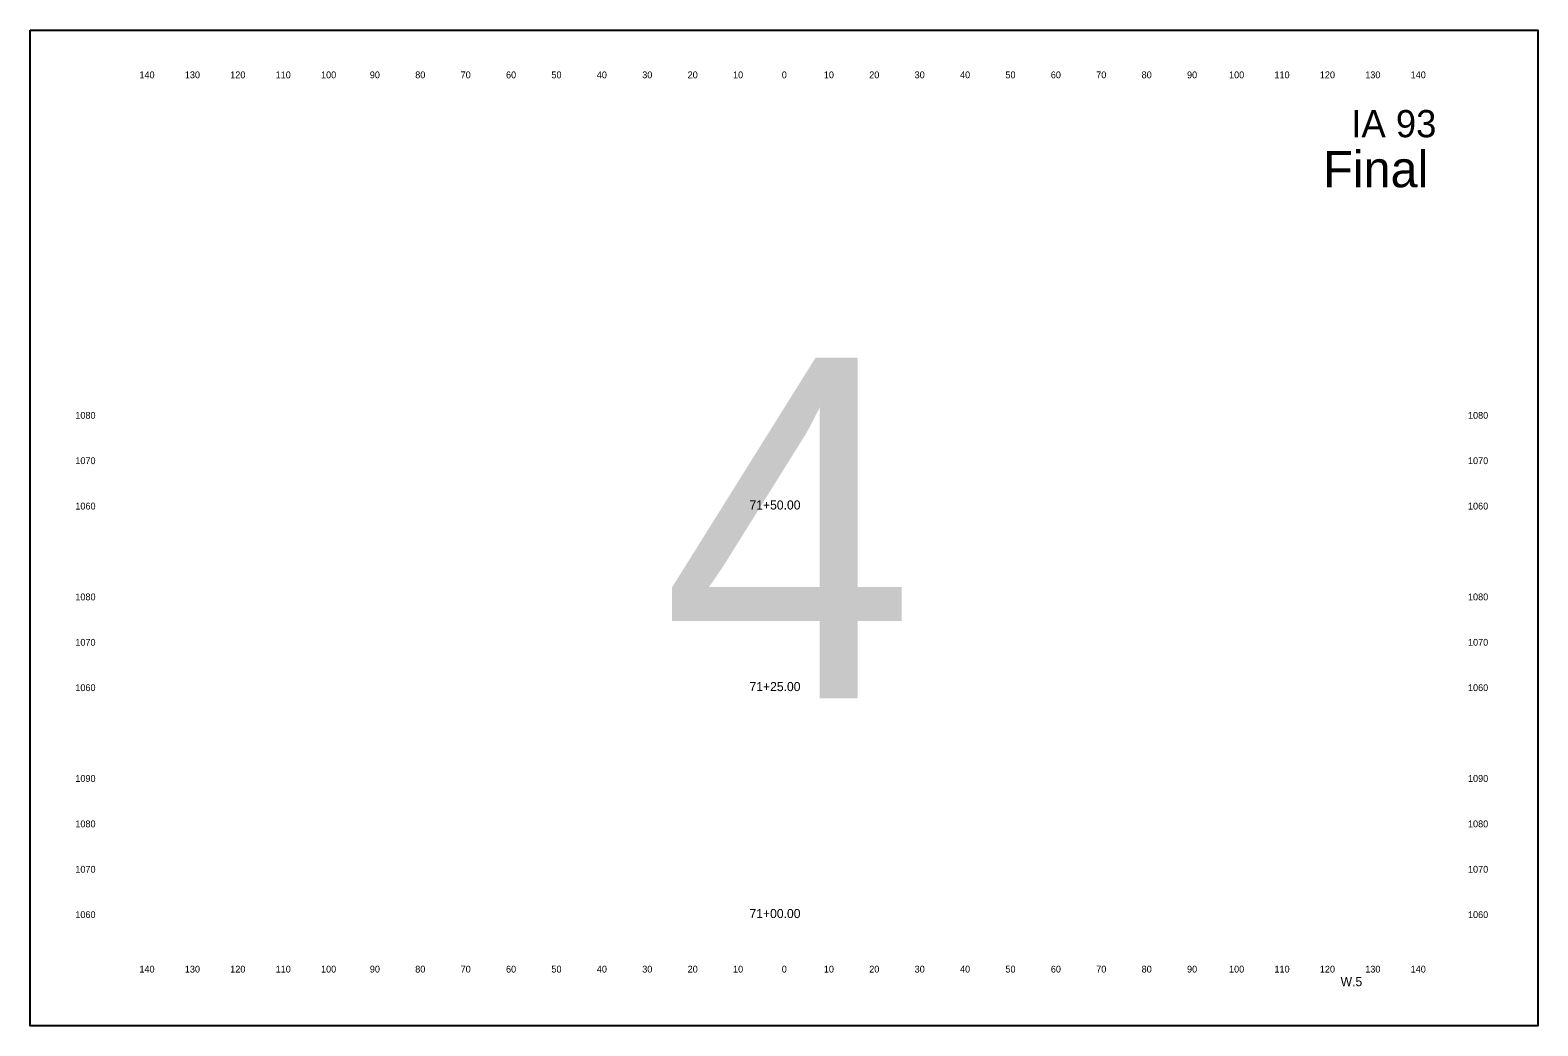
# Model space of a CAD drawing. Extents: x 10123 to 11535, y 9730 to 9950.
# Drawn here: x 11203.2 to 11535.3, y 9730.3 to 9949.6 of the extents above; entities that cross this region are included whole.
import ezdxf

# ---------------------------------------------------------------- set-up
doc = ezdxf.new("R2010")
doc.units = 0
for name, color, linetype in [('dsn3DSubgradeHingePoint', 7, 'Continuous'), ('dsnXSEarthwork', 7, 'Continuous'), ('dsnXsPCCPavement', 7, 'Continuous'), ('dsnXsShldrEarthFill', 7, 'Continuous')]:
    doc.layers.add(name, color=color, linetype=linetype)

msp = doc.modelspace()

# ---------------------------------------------------------------- linework, layer by layer
at = {"layer": 'dsnXsShldrEarthFill'}
msp.add_lwpolyline([(11203.21, 9949.6), (11535.29, 9949.6), (11535.29, 9730.26), (11203.21, 9730.26)], close=True, dxfattribs=at)

# ---------------------------------------------------------------- texts
at = {"layer": 'dsn3DSubgradeHingePoint'}
for s, height, p in [('140', 1.5, (11227.27, 9939)), ('130', 1.5, (11237.27, 9939)), ('120', 1.5, (11247.27, 9939)), ('110', 1.5, (11257.27, 9939)), ('100', 1.5, (11267.27, 9939)), ('90', 1.5, (11278.02, 9939)), ('80', 1.5, (11288.02, 9939)), ('70', 1.5, (11298.02, 9939)), ('60', 1.5, (11308.02, 9939)), ('50', 1.5, (11318.02, 9939)), ('40', 1.5, (11328.02, 9939)), ('30', 1.5, (11338.02, 9939)), ('20', 1.5, (11348.02, 9939)), ('10', 1.5, (11358.02, 9939)), ('0', 1.5, (11368.76, 9939)), ('0', 1.5, (11368.76, 9939)), ('10', 1.5, (11378.02, 9939)), ('20', 1.5, (11388.02, 9939)), ('30', 1.5, (11398.02, 9939)), ('40', 1.5, (11408.02, 9939)), ('50', 1.5, (11418.02, 9939)), ('60', 1.5, (11428.02, 9939)), ('70', 1.5, (11438.02, 9939)), ('80', 1.5, (11448.02, 9939)), ('90', 1.5, (11458.02, 9939)), ('100', 1.5, (11467.27, 9939)), ('110', 1.5, (11477.27, 9939)), ('120', 1.5, (11487.27, 9939)), ('130', 1.5, (11497.27, 9939)), ('140', 1.5, (11507.27, 9939)), ('IA 93', 6, (11494.21, 9926)), ('1080', 1.5, (11213.15, 9864)), ('1080', 1.5, (11519.9, 9864)), ('1070', 1.5, (11213.15, 9854)), ('1070', 1.5, (11519.9, 9854)), ('1060', 1.5, (11213.15, 9844)), ('71+50.00', 2, (11361.65, 9844)), ('1060', 1.5, (11519.9, 9844)), ('1080', 1.5, (11213.15, 9824)), ('1080', 1.5, (11519.9, 9824)), ('1070', 1.5, (11213.15, 9814)), ('1070', 1.5, (11519.9, 9814)), ('1060', 1.5, (11213.15, 9804)), ('71+25.00', 2, (11361.65, 9804)), ('1060', 1.5, (11519.9, 9804)), ('1090', 1.5, (11213.15, 9784)), ('1090', 1.5, (11519.9, 9784)), ('1080', 1.5, (11213.15, 9774)), ('1080', 1.5, (11519.9, 9774)), ('1070', 1.5, (11213.15, 9764)), ('1070', 1.5, (11519.9, 9764)), ('1060', 1.5, (11213.15, 9754)), ('71+00.00', 2, (11361.65, 9754)), ('1060', 1.5, (11519.9, 9754)), ('140', 1.5, (11227.27, 9742)), ('130', 1.5, (11237.27, 9742)), ('120', 1.5, (11247.27, 9742)), ('110', 1.5, (11257.27, 9742)), ('100', 1.5, (11267.27, 9742)), ('90', 1.5, (11278.02, 9742)), ('80', 1.5, (11288.02, 9742)), ('70', 1.5, (11298.02, 9742)), ('60', 1.5, (11308.02, 9742)), ('50', 1.5, (11318.02, 9742)), ('40', 1.5, (11328.02, 9742)), ('30', 1.5, (11338.02, 9742)), ('20', 1.5, (11348.02, 9742)), ('10', 1.5, (11358.02, 9742)), ('0', 1.5, (11368.76, 9742)), ('0', 1.5, (11368.76, 9742)), ('10', 1.5, (11378.02, 9742)), ('20', 1.5, (11388.02, 9742)), ('30', 1.5, (11398.02, 9742)), ('40', 1.5, (11408.02, 9742)), ('50', 1.5, (11418.02, 9742)), ('60', 1.5, (11428.02, 9742)), ('70', 1.5, (11438.02, 9742)), ('80', 1.5, (11448.02, 9742)), ('90', 1.5, (11458.02, 9742)), ('100', 1.5, (11467.27, 9742)), ('110', 1.5, (11477.27, 9742)), ('120', 1.5, (11487.27, 9742)), ('130', 1.5, (11497.27, 9742)), ('140', 1.5, (11507.27, 9742))]:
    msp.add_text(s, height=height, dxfattribs=at).set_placement(p)
at = {"layer": 'dsnXSEarthwork'}
msp.add_text('Final', height=8, dxfattribs=at).set_placement((11488, 9915))
at = {"layer": 'dsnXsPCCPavement'}
msp.add_text('W.5', height=2, dxfattribs=at).set_placement((11491.85, 9739))
at = {"layer": 'dsnXsShldrEarthFill'}
msp.add_text('4', height=75, dxfattribs=at).set_placement((11342.3, 9802.43))

doc.saveas('drawing.dxf')
